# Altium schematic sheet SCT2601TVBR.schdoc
size 127 x 101 mm
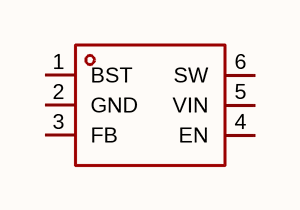
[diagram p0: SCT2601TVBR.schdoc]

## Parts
U?  sct2601tvbr  [TSOT-23-6_L2.9-W1.6-P0.95-LS2.8-BL]  (value not drawn)

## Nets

Not connected (* = marked no-connect by the designer): U? 1(BST) 2(GND) 3(FB) 4(EN) 5(VIN) 6(SW)

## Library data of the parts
U? = sct2601tvbr: 功能类型:降压型;工作电压:4.5V~60V;输出电压:765mV~57V;输出电流:600mA;输出类型:可调;; Manufacturer: SCT(芯洲科技); AddInBom: yes; ModelId: 2c4039b5b88644c1bda4b4ba9e971667; ModelName: TSOT-23-6_L2.9-W1.6-H1.1-LS2.8-P0.95; ModelTransform: 110.236,114.173,0,90,0,0,0,0,0; Function: 降压型; Output Current: 600mA; Frequency - Switching: 700kHz; Synchronous Rectifier: 否; Number of Outputs: 1; Topology: 降压式; Quiescent Current: 80uA; Switch tube (built-in/external): 内置; Output Type: 可调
